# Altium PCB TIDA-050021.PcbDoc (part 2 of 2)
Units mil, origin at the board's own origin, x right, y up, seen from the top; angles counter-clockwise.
Board outline 3800 x 2400 mil, 4 copper layers (Top Layer, Signal Layer 1, Signal Layer 2, Bottom Layer), stack 51.2 mil thick; 78 components, 31 nets, 172 pads, 126 vias.
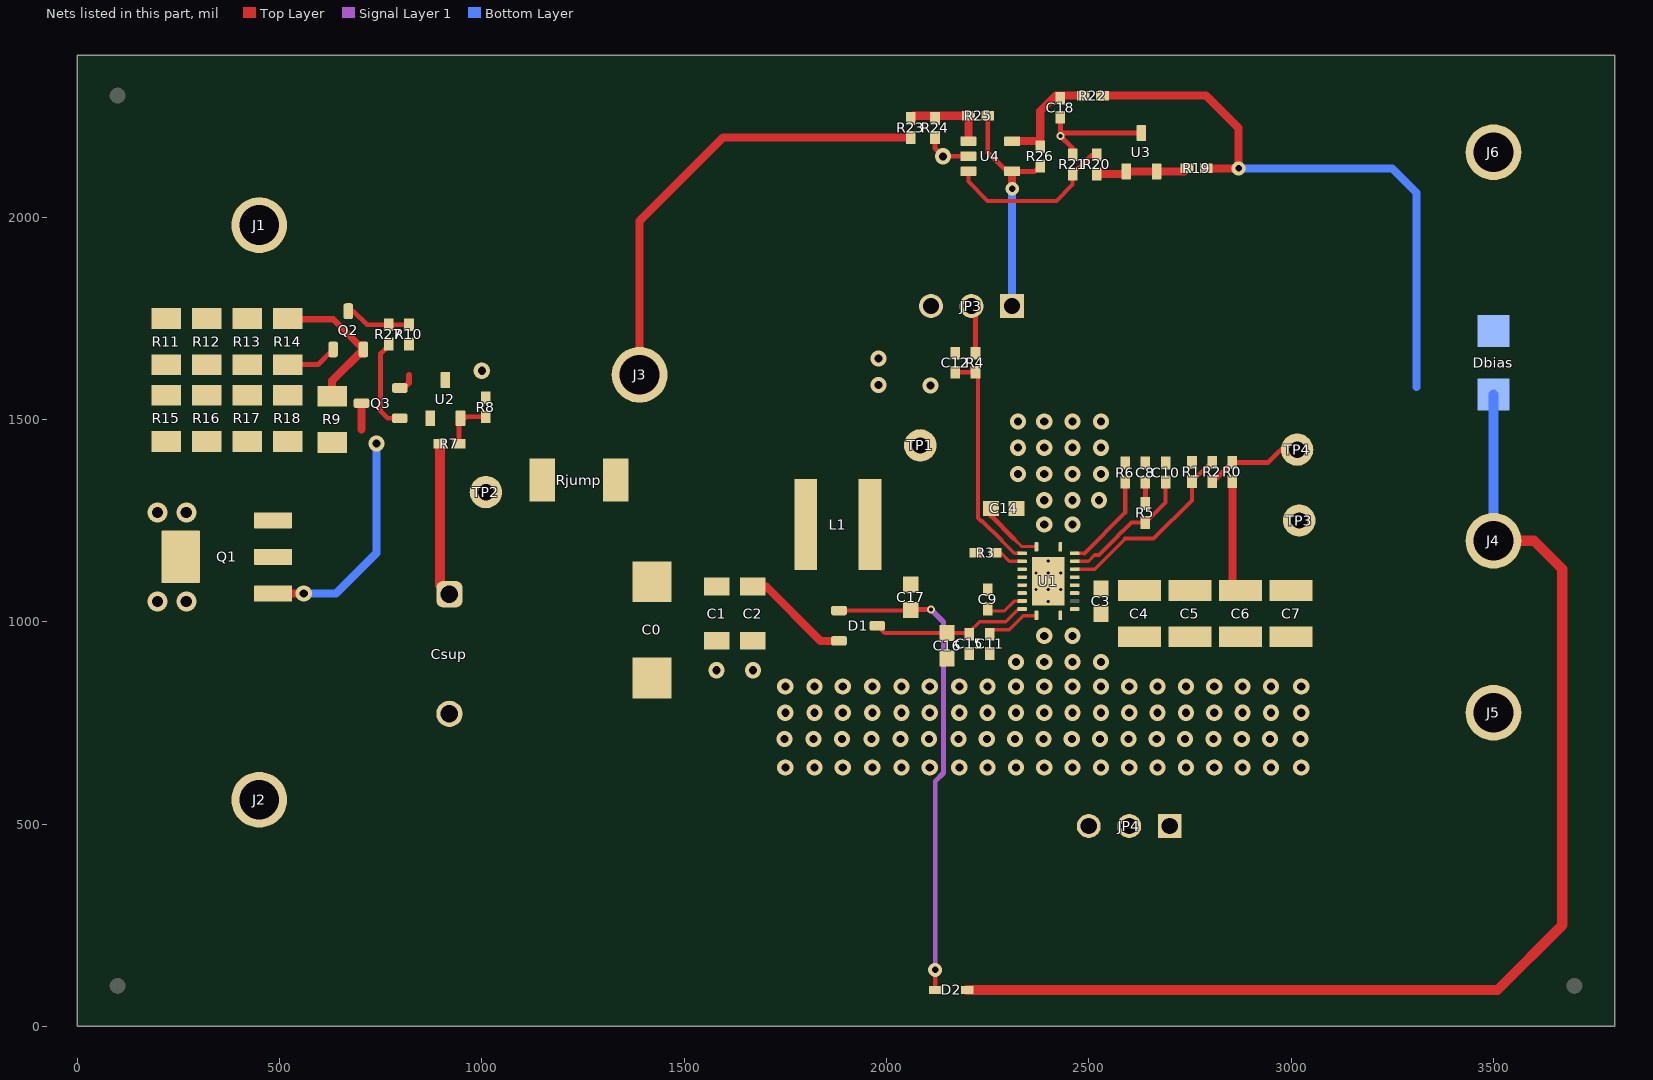
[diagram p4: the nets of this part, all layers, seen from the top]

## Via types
v1: diameter 40, hole 20, Top Layer to Bottom Layer, 108 vias
v2: diameter 19.68, hole 7.87, Top Layer to Bottom Layer, 8 vias
v3: diameter 34, hole 16, Top Layer to Bottom Layer, 4 vias
v4: diameter 50, hole 28, Top Layer to Bottom Layer, 4 vias
v5: diameter 20, hole 10, Top Layer to Bottom Layer, 2 vias

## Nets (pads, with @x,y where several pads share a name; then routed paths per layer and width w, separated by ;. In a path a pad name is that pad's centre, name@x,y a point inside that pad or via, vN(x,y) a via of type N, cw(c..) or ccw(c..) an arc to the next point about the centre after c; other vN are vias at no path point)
2.5V: R7.1 R8.2 U2.2 | length 142.5
  Top Layer w12: U2.2@941.16,1506.38 R8.2@1010,1506.38 ; R7.1@943.62,1440 943.62,1488.98 961.09,1506.45
AGND: C0.2 C1.2 C2.2 C3.2 C4.2 C5.2 C6.2 C7.2 C8.2 C10.2 C11.1 C12.2 C14.1 C15.2 C16.2 C18.2 Csup.2 J2.1 J5.1 JP3.3 JP4.1 JP4.2 JP4.3 Q3.2 R1.1 R6.1 R8.1 R10.1 R21.1 R24.1 U1.11 U1.12 U1.20 U1.21@2400,1100 U2.3 U3.3 U4.2 | length 467.8
  Top Layer w12: Q3.2@797.24,1577.4 Q3.2@807.4,1577.4 ; R24.1@2120,2196.38 2120,2170 2139.8,2150.2 U4.2@2202.43,2150.2 U4.2@2205.85,2153.62 ; C18.2@2430,2246.38 v5(2430,2200) 2460,2170 R21.1@2460,2153.62 ; 2437.24,2207.24 U3.3@2630,2207.24
  Top Layer w15: Q3.2@807.4,1577.4 820,1590 820,1610
  other v1: 1750,640 1822,640 1892,640 1965,640 2037,640 2107,640 2180,640 2250,640 2320,640 2390,640 2460,640 2530,640 2600,640 2670,640 2740,640 2810,640 2880,640 2950,640 3025,640 1748,710 1820,710 1890,710 1963,710 2035,710 2105,710 2178,710 2248,710 2318,710 2388,710 2458,710 2528,710 2598,710 2668,710 2738,710 2808,710 2878,710 2948,710 3023,710 1750,775 1822,775 1892,775 1965,775 2037,775 2107,775 2180,775 2250,775 2320,775 2390,775 2460,775 2530,775 2600,775 2670,775 2740,775 2810,775 2880,775 2950,775 3025,775 1750,840 1822,840 1892,840 1965,840 2037,840 2107,840 2180,840 2250,840 2320,840 2390,840 2460,840 2530,840 2600,840 2670,840 2740,840 2810,840 2880,840 2950,840 3025,840 1580,880 1670,880 2320,900 2390,900 2460,900 2530,900 2390,965 2460,965 2390,1240 2460,1240 2390,1300 2460,1300 2525,1300 2325,1365 2390,1365 2460,1365 2530,1365 2325,1430 2390,1430 2460,1430 2530,1430 2325,1495 2390,1495 2460,1495 2530,1495 2109,1584 1980,1585 1000,1620 1980,1650 2140,2150
  other v2: 2400,1049.8 2369.49,1079.33 2400,1079.33 2430.51,1079.33 2369.49,1120.67 2400,1120.67 2430.51,1120.67 2400,1150.2
BOOT: C9.2 U1.8 | length 90.1
  Top Layer w8: C9.2@2255,1026.38 2291.38,1026.38 2315.78,1050.78 U1.8@2335.04,1050.78
COMP: C10.1 R5.2 U1.18 | length 335.6
  Top Layer w8: U1.18@2464.96,1149.21 2499.21,1149.21 2515,1165
  Top Layer w10: 2515,1165 2525,1165 2572.13,1212.13 2572.13,1212.4 2582.6,1222.87 2582.87,1222.87 2605,1245 R5.2@2640,1245 2690,1295 C10.1@2690,1345
EN: C12.1 R4.2 U1.2 | length 539.6
  Top Layer w8: 2285,1200 2316.11,1168.89 U1.2@2335.04,1168.89
  Top Layer w10: C12.1@2170,1616.38 R4.2@2220,1616.38 ; 2225.94,1600.43 2225.94,1255.97 2233.49,1248.43 2236.57,1248.43 2285,1200
EN1: JP3.1 R25.2 R26.1 U4.4 | length 578.4
  Top Layer w12: R25.2@2250.18,2250.2 2250.18,2159.82 2297.21,2112.79 U4.4@2310.69,2112.79 2366.42,2112.79 R26.1@2380,2126.38
  Top Layer w20: v3(2310.69,2070) U4.4@2310.69,2112.79
  Bottom Layer w20: JP3.1@2310,1780 2310,2069.31 v3(2310.69,2070)
FB: R1.2 R2.1 U1.17 | length 476.6
  Top Layer w8: U1.17@2464.96,1129.52 2514.52,1129.52 2590,1205
  Top Layer w10: 2590,1205 2660,1205 2755,1300 R1.2@2755,1346.38 2802.24,1393.62 R2.1@2805,1393.62
FSW: R3.1 U1.3 | length 75
  Top Layer w8: R3.1@2268.62,1170 2283,1170 2303.79,1149.21 U1.3@2335.04,1149.21
ILIM: R6.2 U1.19 | length 241.9
  Top Layer w8: U1.19@2464.96,1168.89 2488.89,1168.89
  Top Layer w10: 2488.89,1168.89 2590,1270
  Top Layer w12: 2590,1270 R6.2@2590,1345
NetC8_1: C8.1 R5.1 | length 52.8
  Top Layer w12: R5.1@2640,1292.24 C8.1@2640,1345
NetC17_2: C17.2 D1.1 D2.1 | length 1190.4
  Top Layer w10: D1.1@1882.76,1027.4 2058.9,1027.4 C17.2@2060,1028.5
  Top Layer w12: C17.2@2060,1028.5 2061.5,1030 v5(2110,1030) ; D2.1@2120.63,90 v3(2120.63,139.37)
  Signal Layer 1 w12: v5(2110,1030) 2140.87,999.13 2140.87,625.97 2120.63,605.72 v3(2120.63,139.37) v3(2120,140)
NetJP3_2: JP3.2 R4.1 | length 116.4
  Top Layer w12: R4.1@2220,1663.62 JP3.2@2220,1780
NetQ1_1: Q1.1 Q3.3 R9.2 U2.1 | length 652.7
  Top Layer w12: v1@559.45,1069.45 v1(560,1070) ; R9.2@630,1462.91 R9.2@642.91,1450 ; v1@737.87,1440 v1(740,1440)
  Top Layer w20: Q1.1@484.17,1069.45 v1@559.45,1069.45 ; 702.76,1475.12 Q3.3@702.76,1540
  Bottom Layer w20: v1(560,1070) 640,1070 740,1170 v1(740,1440)
NetQ1_2: Q1.2 Q1.4 R15.2 R16.2 R17.2 R18.2 | length 23.4
  Top Layer w20: Q1.4@272.36,1176.54 Q1.4@288.9,1160
  other v4: 198.74,1050 270,1050 198.74,1270 270,1270
NetQ2_1: Q2.1 R11.2 R12.2 R13.2 R14.2 R15.1 R16.1 R17.1 R18.1 | length 142.3
  Top Layer w12: R14.2@520,1635.28 595.12,1635.28 Q2.1@632.6,1672.76
  Top Layer w20: R11.2@210,1630 R11.2@220,1620
NetQ2_3: Q2.3 R10.2 R27.1 | length 163.9
  Top Layer w12: Q2.3@670,1767.24 682.76,1767.24 716.38,1733.62 R27.1@770,1733.62 R10.2@820,1733.62
NetQ3_1: Q3.1 R27.2 | length 229.1
  Top Layer w12: R27.2@770,1686.38 770,1682.44 750,1662.44 750,1520 767.4,1502.6 Q3.1@797.24,1502.6
NetR0_1: R0.1 R2.2 TP4.1 | length 237.9
  Top Layer w12: R2.2@2805,1346.38 2807.76,1346.38 R0.1@2855,1393.62 2943.62,1393.62 TP4.1@3000,1450
NetR19_2: R19.2 R20.1 U3.1 U3.2 | length 228.7
  Top Layer w20: R20.1@2520,2106.38 2586.22,2106.38 U3.1@2592.6,2112.76 U3.2@2667.4,2112.76 2735.5,2112.76 R19.2@2742.94,2120.2
NetR23_1: R23.1 R24.2 R25.1 U4.1 | length 208.5
  Top Layer w20: R23.1@2060,2243.62 2066.57,2250.2 R25.1@2202.94,2250.2 2202.94,2188.11 U4.1@2202.43,2187.6
SS: C11.2 U1.10 | length 134.8
  Top Layer w8: C11.2@2255,968.62 2266.38,980 2303.32,980 2337.82,1014.5 2369.62,1014.5 U1.10@2370.48,1015.35
SVin: C15.1 C16.1 D1.3 U1.9 | length 396.3
  Top Layer w8: C15.1@2205,968.62 2205,975 2230,1000 2295,1000 2326.1,1031.1 U1.9@2335.04,1031.1
  Top Layer w10: D1.3@1977.24,990 1995.75,971.5 C16.1@2150,971.5 2202.13,971.5 C15.1@2205,968.62
SW: C9.1 C17.1 L1.2 R3.2 TP1.1 U1.4 U1.5 U1.6 U1.7
V+: C18.1 R22.1 R26.2 U4.5 | length 269.2
  Top Layer w20: U4.5@2310.69,2187.6 2380,2187.6 R26.2@2380,2173.62 ; 2380,2198 2380,2261.65 2418.35,2300 R22.1@2486.38,2300
Vbias: Dbias.2 J6.1
Vcc: C14.2 U1.1 | length 175
  Top Layer w8: 2315,1205 2334.19,1185.81 2334.19,1185.49 2370.48,1185.49 U1.1@2370.48,1184.65
  Top Layer w12: C14.2@2258.5,1280 2258.5,1261.5 2315,1205
  Top Layer w15: C14.2@2260,1288.5 C14.2@2268.5,1280
Vin: J1.1 Q2.2 R9.1 R11.1 R12.1 R13.1 R14.1 | length 352.5
  Top Layer w12: R14.1@520,1749.45 R14.1@521.89,1747.56
  Top Layer w16: R14.1@521.89,1747.56 632.6,1747.56 Q2.2@707.4,1672.76
  Top Layer w20: R9.1@630,1571.5 630,1595.35 Q2.2@707.4,1672.76
Vout: C3.1 C4.1 C5.1 C6.1 C7.1 D2.2 Dbias.1 J4.1 R0.2 R19.1 R22.2 TP3.1 U1.14 U1.15 U1.16 | length 4742.6
  Top Layer w20: R22.2@2540,2300 2790,2300 2870,2220 v3(2870,2120) 2790.38,2120 R19.1@2790.18,2120.2 ; R0.2@2855,1346.38 2855,1097.09 C6.1@2875,1077.09
  Top Layer w25: D2.2@2199.37,90 3510,90 3670,250 3670,1130 3600,1200 J4.1@3500,1200
  Bottom Layer w20: v3(2870,2120) 3250,2120 3310,2060 3310,1580
  Bottom Layer w25: J4.1@3500,1200 Dbias.1@3500,1561.26
Vref: R20.2 R21.2 U4.3 | length 425
  Top Layer w10: U4.3@2202.43,2112.79 2202.43,2087.57 2250,2040 2420,2040 2460,2080 R21.2@2460,2106.38 2507.24,2153.62 R20.2@2520,2153.62
VSUP: Csup.1 Q1.3 R7.2 Rjump.2 TP2.1 | length 382.1
  Top Layer w25: R7.2@896.38,1440 896.38,1091.26 Csup.1@920,1067.64
VSUP1: C0.1 C1.1 C2.1 D1.2 J3.1 L1.1 R23.2 Rjump.1 | length 1413.9
  Top Layer w20: J3.1@1390,1600 1390,1990 1596.38,2196.38 R23.2@2060,2196.38 ; C2.1@1670,1086.93 1703.07,1086.93 1837.4,952.6 D1.2@1882.76,952.6
pads on no net: FID1.1 FID2.1 FID3.1 U1.13 U1.21@2377.95,1058.66 U1.21@2377.95,1100 U1.21@2377.95,1141.34 U1.21@2422.05,1058.66 U1.21@2422.05,1100 U1.21@2422.05,1141.34

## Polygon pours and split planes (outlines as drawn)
AGND on Top Layer "TOP_LAYER_AGND_P008" (solid, remove dead copper, pour order 8): 1900,1560 1900,2000 3500,2000 3600,1900 3600,1380 2770,1380 2580,1380 2560,1360 2560,1270 2430.51,1140.51 2430.51,1120.67 2369.49,1120.67 2370,1121.18 2370,1181.18 2301.18,1250 2280,1250 2280,1560
AGND on Top Layer "TOP_LAYER_AGND_P006" (solid, remove dead copper, pour order 6): 400,980 1700,980 1750,930 2270,930 2370,1030 2370,1050 2440,1050 2452,1038 2554,1038 2592,1000 3600,1000 3600,300 3500,200 500,200 400,300
SW on Top Layer "TOP_LAYER_SW_P004" (solid, remove dead copper, pour order 4): 1900,1465 1965,1465 2105,1465 2200,1370 2200,1240 2231.24,1208.76 2231.24,1158.17 2249.41,1140 2300,1140 2306,1134 2345,1134 2345,1060 2235,1060 1900,1060
VSUP1 on Top Layer "TOP_LAYER_VSUP1_P002" (solid, remove dead copper, pour order 2): 1240,1940 1300,2000 1840,2000 1840,1040 1240,1040
Vout on Top Layer "TOP_LAYER_VOUT_P000" (solid, remove dead copper, pour order 0): 2485,1115 2525.09,1115.09 2590,1180 2670,1180 2790,1300 3600,1300 3600,1030 2600,1030 2568,1062 2485,1062 2482,1065 2454,1065 2454,1115
Vin on Top Layer "TOP_LAYER_VIN_P012" (solid, remove dead copper, pour order 12): 200,1900 300,2000 570,2000 570,1720 200,1720
NetQ2_1 on Top Layer "TOP_LAYER_NETQ2_1_P014" (solid, remove dead copper, pour order 14): 200,1660 566.26,1660 566.26,1530 200,1530
NetQ1_2 on Top Layer "TOP_LAYER_NETQ1_2_P016" (solid, remove dead copper, pour order 16): 180,1480 566.26,1480 566.26,1366.26 530,1330 400,1330 400,1210 425.12,1184.88 425.12,1180 530,1180 530,1140 425.12,1140 400,1114.88 400,990 180,990
AGND on Top Layer "TOP_LAYER_AGND_P026" (solid, remove dead copper, pour order 26): 810,1700 1000,1700 1020,1680 1020,1540 1000,1540 940,1600 810,1600
VSUP on Top Layer "TOP_LAYER_VSUP_P042" (solid, remove dead copper, pour order 42): 440,1310 910,1310 1050,1450 1050,1560 1070,1580 1190,1580 1190,1040 600,1040 600,1180 570,1210 440,1210
NetQ1_1 on Top Layer "TOP_LAYER_NETQ1_1_P044" (solid, remove dead copper, pour order 44): 640,1460 640,1475 645,1480 826.1,1480 841.1,1495 841.1,1520 879.69,1520 885,1514.69 885,1485 800,1400 595,1400 595,1455 637.91,1455
Vout on Bottom Layer "BOTTOM_LAYER_VOUT_P038" (solid, remove dead copper, pour order 38): 3300,1600 3700,1600 3700,1130 3670,1100 3322.5,1100 3300,1130 3300,1150
NetQ1_2 on Bottom Layer "BOTTOM_LAYER_NETQ1_2_P022" (solid, remove dead copper, pour order 22): 180,1420 520,1420 520,990 180,990
AGND on Bottom Layer "BOTTOM_LAYER_AGND_P034" (solid, remove dead copper, pour order 34): 1064.71,1900 3100,1900 3250,1750 3250,360 3090,200 500,200 400,300 400,830 550,980 930,980 980,1030 980,1815.29
Vbias on Bottom Layer "BOTTOM_LAYER_VBIAS_P040" (solid, remove dead copper, pour order 40): 3340,2300 3700,2300 3700,1690 3340,1690
NetQ1_2 on Signal Layer 1 "SIGNAL_LAYER_1_NETQ1_2_P018" (solid, remove dead copper, pour order 18): 510,1400 510,990 160,990 160,1400
AGND on Signal Layer 1 "SIGNAL_LAYER_1_AGND_P030" (solid, remove dead copper, pour order 30): 1100,2000 3500,2000 3600,1900 3600,300 3500,200 500,200 400,300 400,830 550,980 930,980 980,1030 980,1880
NetQ1_2 on Signal Layer 2 "SIGNAL_LAYER_2_NETQ1_2_P020" (solid, remove dead copper, pour order 20): 160,1400 510,1400 510,990 160,990
AGND on Signal Layer 2 "SIGNAL_LAYER_2_AGND_P032" (solid, remove dead copper, pour order 32): 980,1900 1290,2210 3290,2210 3600,1900 3600,300 3500,200 500,200 400,300 400,830 550,980 930,980 980,1030

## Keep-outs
Keep-Out Layer:
  text ".Layer_Name" at 577,-858.49 h30

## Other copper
Top Layer:
  pour cut-out: 400,979.8 549.97,979.97 400.98,830.98 400.98,980
  text ".Layer_Name" at 577,-858.49 h30
Bottom Layer:
  text ".Layer_Name" at 577,-858.49 h30

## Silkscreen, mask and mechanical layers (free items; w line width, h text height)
Top Overlay:
  text "Vbias" at 3410,2280 h30
  text "VIN" at 400,2100 h50
  text "OFF" at 2060,1860 h30
  text "EN" at 2180,1860 h30
  text "ON" at 2280,1860 h30
  text "Vsup" at 1500,1520 h50
  text "VO" at 3650,1160 h50
  text "GND" at 3635,730 h50
  text "GND" at 380,380 h50
  text "GND" at 2500,360 h50
  text "TIDA-050021" at 1000,235 h60
  text ".Layer_Name" at 577,-858.49 h30
Bottom Overlay:
  text ".Layer_Name" at 577,-858.49 h30
Top Paste:
  text ".Layer_Name" at 577,-858.49 h30
Bottom Paste:
  text ".Layer_Name" at 577,-858.49 h30
Top Solder:
  text ".Layer_Name" at 577,-858.49 h30
  text ".Layer_Name" at 577,-858.49 h30
Bottom Solder:
  text ".Layer_Name" at 577,-858.49 h30
Drill Guide:
  text ".Layer_Name" at 577,-858.49 h30
M1 Board Outline:
  lines w10: 0,0 0,2400 ; 0,0 3800,0 ; 0,0 0,2400 ; 0,0 3800,0 ; 0,2400 3800,2400 ; 0,2400 3800,2400 ; 3800,0 3800,2400 ; 3800,0 3800,2400
  text ".Layer_Name" at 577,-858.49 h30
M2 Board Dimensions:
  rectangle: 125,-400 500,-275
  rectangle: 0,-275 125,-150
  lines w7: 0,-275 1000,-275 ; 125,-400 125,-150 ; 250,-400 250,-150 ; 500,-400 500,-150 ; 750,-400 750,-150 ; 0,-400 0,-150 1000,-150 1000,-400 0,-400
  text ".Layer_Name" at 577,-858.49 h30
M3 3D STEP Top:
  text ".Layer_Name" at 577,-858.49 h30
M4 3D STEP Bottom:
  text ".Layer_Name" at 577,-858.49 h30
M5 Assembly Top:
  lines w10: -292,-930.17 6308,-930.17 ; -292,-726.83 6310,-726.83 ; -292,-523.5 -292,-1133.5 3713,-1133.5 6310,-1133.5 6310,-523.5 -291.5,-523.5 -291.5,-1133.5 1284,-1133.5 ; 2173,-1133.5 2173,-523.5 ; 3440,-726.83 3440,-523.5 ; 4280,-726.83 4280,-523.5 ; 4902,-1140 4902,-937.17
  text "COMPONENTS MARKED 'DNP' SHOULD NOT BE POPULATED." at 1153.5,-318.5 h30
  text "ASSEMBLY VARIANT:" at 1153,-434 h30
  text ".VariantName" at 2189,-434 h30
  text "PCB VIEWED FROM TOP SIDE" at -228.5,-655.67 h30
  text "BOARD #:" at 2248,-655.67 h30
  text ".PRJ_Number" at 2793.5,-655.67 h30
  text "REV:" at 3638,-655.67 h30
  text ".PCB_Rev" at 3929.5,-655.67 h30
  text "SVN REV:" at 4476,-655.67 h30
  text ".VersionControl_RevNumber" at 4982,-655.67 h30
  text "TID #:" at 2248,-859 h30
  text ".TID" at 2793.5,-859 h30
  text "PLOT NAME =" at -228.5,-1064.34 h30
  text ".plot_File_Name" at 577,-1064.34 h30
  text "GENERATED    :" at 2250,-1064.34 h30
  text ".Print_Date" at 3119.5,-1064.34 h30
  text ".Print_Time" at 3848.5,-1064.34 h30
  text "TEXAS INSTRUMENTS" at 5113,-1064.34 h30
M6 Assembly Bottom:
  lines w10: -292.5,-727.33 6309.5,-727.33 ; -290.5,-930.67 6309.5,-930.67 ; 1115.5,-1140.5 1115.5,-937.67 ; 1737.5,-727.33 1737.5,-524 ; 2577.5,-727.33 2577.5,-524 ; 3844.5,-1134 3844.5,-524 ; 4733.5,-1134 6309,-1134 6309,-524 -292.5,-524 -292.5,-1134 2304.5,-1134 6309.5,-1134 6309.5,-524
  text "COMPONENTS MARKED 'DNP' SHOULD NOT BE POPULATED." at 6102,-318 h30
  text ".VariantName" at 5058,-434 h30
  text "ASSEMBLY VARIANT:" at 6097,-434 h30
  text ".VersionControl_RevNumber" at 1035.5,-656.17 h30
  text "SVN REV:" at 1541.5,-656.17 h30
  text ".PCB_Rev" at 2088,-656.17 h30
  text "REV:" at 2379.5,-656.17 h30
  text ".PRJ_Number" at 3224,-656.17 h30
  text "BOARD #:" at 3769.5,-656.17 h30
  text "PCB VIEWED FROM BOTTOM SIDE" at 6246,-656.17 h30
  text ".TID" at 3224,-859.5 h30
  text "TID #:" at 3769.5,-859.5 h30
  text "TEXAS INSTRUMENTS" at 904.5,-1064.84 h30
  text ".Print_Time" at 2169,-1064.84 h30
  text ".Print_Date" at 2898,-1064.84 h30
  text "GENERATED    :" at 3767.5,-1064.84 h30
  text ".plot_File_Name" at 5440.5,-1064.84 h30
  text "PLOT NAME =" at 6246,-1064.84 h30
M9 Title Sheet:
  drawing of 57 lines, arcs and shapes, not listed
  text "1" at 739.84,8036.5 h30
  text "2" at 3235.5,8036.5 h30
  text "3" at 5724.84,8036.5 h30
  text "4" at 8231.51,8036.5 h30
  text "5" at 10730.5,8036.5 h30
  text "6" at 13235.5,8036.5 h30
  text "A" at -416.5,6893.5 h30
  text "A" at 14383.5,6893.5 h30
  text "B" at -416.5,4513.5 h30
  text "B" at 14383.5,4513.5 h30
  text "C" at -416.5,2138.5 h30
  text "C" at 14383.5,2138.5 h30
  text "PROJECT TITLE:" at 11343.5,277.5 h30
  text ".PRJ_Title" at 11393.5,144.17 h30
  text "DESIGNED FOR:" at 11343.5,-23.5 h30
  text ".PRJ_Customer" at 11393.5,-163.5 h30
  text "D" at -416.5,-231.5 h30
  text "D" at 14383.5,-231.5 h30
  text "FILE NAME:" at 11343.5,-323.5 h30
  text ".PCB_File_Name_No_Path" at 11393.5,-443.5 h30
  text "Texas Instruments (TI) and/or its licensors do not warrant the accuracy or completeness of this specification" at 6374,-605.34 h30
  text "ENGINEER:" at 11343.5,-613.5 h30
  text "LAYOUT BY:" at 12848.5,-613.5 h30
  text "or any information contained therein. TI and/or its licensors do not warrant that this design will meet" at 6329.01,-718 h30
  text ".PRJ_Engineer" at 11393.5,-768.49 h30
  text ".PCB_Layout" at 12899,-768.49 h30
  text "the specifications, will be suitable for your application or fit for any particular purpose, or will operate in" at 6329.01,-830.67 h30
  text ".Layer_Name" at 577,-858.49 h30
  text "ALTIUM DESIGNER VERSION:" at 12848.5,-923.5 h30
  text "an implementation. TI and/or its licensors do not warrant that the design is production worthy. You should" at 6329.01,-943.33 h30
  text "completely validate and test your design implementation to confirm the system functionality for your application." at 6374,-1056 h30
  text ".print_Scale" at 11393.5,-1056.83 h30
  text ".Application_BuildNumber" at 12899,-1056.83 h30
  text "1" at 739.84,-1263.5 h30
  text "2" at 3235.5,-1263.5 h30
  text "3" at 5724.84,-1263.5 h30
  text "4" at 8231.51,-1263.5 h30
  text "5" at 10730.5,-1263.5 h30
  text "6" at 13235.5,-1263.5 h30
M10 Fab Notes:
  drawing of 189 lines, arcs and shapes, not listed
  text "DESIGN INFORMATION" at 12382.02,6356.17 h30
  text "MIN. TRACK WIDTH:" at 11737.46,6224.05 h30
  text "8" at 12833.7,6224.05 h30
  text "MIL" at 12988.46,6224.05 h30
  text "MIN. CLEARANCE:" at 11737.46,6099.92 h30
  text "0.1" at 12773.7,6099.93 h30
  text "mm" at 12988.46,6099.92 h30
  text "MIN. VIA PAD SIZE:" at 11737.46,5975.8 h30
  text "18" at 12803.71,5975.8 h30
  text "MIL" at 12988.46,5975.8 h30
  text "0.05mm (2MIL)" at 12432.46,5845.9 h30
  text "MINIMUM ANNULAR RING" at 11408.23,5837.67 h30
  text "EXTERNAL" at 13140.46,5837.67 h30
  text "PER" at 11608.23,5727.55 h30
  text "IPC-D-275 CLASS 2 LEVEL C" at 11828.23,5727.54 h30
  text "MIL, HOLES" at 13316.46,5627.07 h30
  text "+/-" at 12924,5618.48 h30
  text "+/-" at 13778,5618.48 h30
  text "REGISTRATION TOLERANCES:" at 11408.23,5617.42 h30
  text "METAL" at 12608,5617.42 h30
  text "5" at 13184.2,5617.42 h30
  text "3" at 14017.2,5617.42 h30
  text "MIL" at 14133.46,5617.42 h30
  text "HOLE SIZE TOLERANCE (UNLESS OTHERWISE SPECIFIED):" at 11408.23,5519.1 h30
  text "+/-" at 13778,5516.23 h30
  text "3" at 14017.2,5515.17 h30
  text "MIL" at 14133.46,5515.17 h30
  text "MATERIAL:" at 11333.46,5377.52 h30
  text "FR-4 High Tg" at 12319.9,5249 h30
  text "X" at 12175.46,5241.01 h30
  text "FR-408" at 11754.46,5236.49 h30
  text "OTHER" at 13242.46,5236.49 h30
  text "X" at 13250.46,5101.01 h30
  text "62 MIL (1.6mm) +/-10%" at 12074.56,5093.46 h30
  text "47mil(1.2mm)" at 13655,5089 h30
  text "THICKNESS:" at 11408.23,5085.24 h30
  text "OTHER" at 13359.46,5085.24 h30
  text "TOLERANCE:" at 11408.23,4946.92 h30
  text "X" at 12256.46,4946.92 h30
  text "ANSI IPC-6012 TYPE 3 CLASS 2" at 12434.48,4946.92 h30
  text "OTHER +/-" at 12434.46,4802.73 h30
  text "BOW & TWIST:" at 11408.23,4657.54 h30
  text "X" at 12256.46,4657.54 h30
  text "ANSI IPC-6012 TYPE 3 CLASS 2" at 12434.48,4657.54 h30
  text "OTHER +/-" at 12434.46,4510.85 h30
  text "DRILLING:" at 11333.46,4380.23 h30
  text "NC_DRILL FILES" at 13094.46,4275.04 h30
  text "REFERENCE:" at 11408.23,4271.1 h30
  text "X" at 12065.46,4271.01 h30
  text "AS SHOWN" at 12243.46,4271.1 h30
  text "X" at 12966.46,4271.1 h30
  text "OTHER" at 13392.46,4128.85 h30
  text "PTH COPPER THICKNESS:" at 11407.91,4125.32 h30
  text "X" at 12547.14,4125.32 h30
  text "20-30 um" at 12675.14,4125.32 h30
  text "BOARD FINISH:" at 11333.46,3977.73 h30
  text "SILKSCREEN:" at 11488.68,3867.6 h30
  text "X" at 12446.46,3867.6 h30
  text "TOP" at 12563.46,3867.6 h30
  text "X" at 12956.46,3867.6 h30
  text "BOTTOM" at 13074.46,3867.6 h30
  text "SILKSCREEN COLOR:" at 11488.68,3712.41 h30
  text "X" at 12445.46,3712.41 h30
  text "WHITE" at 12563.46,3712.41 h30
  text "OTHER" at 13074.46,3712.41 h30
  text "X" at 12576.46,3568.96 h30
  text "GREEN" at 12694.46,3568.96 h30
  text "OTHER" at 13312.46,3568.96 h30
  text "SOLDER RESIST COLOR:" at 11488.68,3562.1 h30
  text "X" at 12576.46,3414.71 h30
  text "MATTE" at 12694.46,3414.71 h30
  text "SEMI-GLOSS" at 13312,3414.07 h30
  text "IMMERSION GOLD (ENIG)" at 12394.46,3241.94 h30
  text "ENEPIG" at 13732,3234.72 h30
  text "SURFACE FINISH:" at 11333.46,3233.72 h30
  text "X" at 12216.46,3233.72 h30
  text "IMM. TIN/SILVER OR EQUIV" at 11663,3096.4 h30
  text "OTHER" at 13094.46,3092.47 h30
  text "ARRAY/PANEL:" at 11333.46,2937.09 h30
  text "CUT AND TRIM PER M1 BOARD OUTLINE" at 12394.46,2928.87 h30
  text "N.C. ROUTE" at 12394.46,2792.9 h30
  text "X" at 13082.46,2792.9 h30
  text "V. SCORE" at 13260.46,2792.9 h30
  text "CERTIFICATION:" at 11333.46,2663.77 h30
  text "MATERIALS AND WORKMANSHIP FOR ALL PCBS" at 12058.46,2663.77 h30
  text "TO MEET OR EXCEED THE REQUIREMENTS OF:" at 12058.46,2569.71 h30
  text "X" at 11695.97,2441.08 h30
  text "ANSI IPC-A-600F CLASS ->" at 11823.96,2441.08 h30
  text "X" at 13471.97,2441.08 h30
  text "2" at 13581.96,2441.08 h30
  text "1" at 13266.96,2439.58 h30
  text "3" at 13935.96,2439.58 h30
  text "X" at 12507.97,2293.39 h30
  text "RoHS" at 12635.96,2293.39 h30
  text "OTHER" at 13280.36,2293.39 h30
  text "PER ORDER" at 13677.42,2293.39 h30
  text "ALL BOARDS MUST MEET OR EXCEED UL94-V0 REQUIREMENTS." at 11361,2139.57 h30
  text "PCB MUST BEAR THE UL94V-0 UL REGISTERED MATERIAL ID NUMBER" at 11361,2023.5 h30
  text "ADDITIONAL REQUIREMENTS:" at 11333.46,1854.08 h30
  text "MICROSECTION:" at 11408.23,1746.95 h30
  text "YES" at 12313.96,1746.95 h30
  text "REQUIRED" at 13175.46,1602.62 h30
  text "BARE BOARD ELEC. TEST:" at 11408.23,1599.76 h30
  text "NONE" at 12713.96,1599.76 h30
  text "X" at 13057.46,1599.76 h30
  text "PER ORDER" at 13767.46,1599.76 h30
  text "XX MIL VIAS REQUIRE NON-CONDUCTIVE FILL AND PLANARIZE" at 11576.38,1394.82 h30
  text "XX MIL VIAS REQUIRE CONDUCTIVE FILL AND PLANARIZE" at 11584.38,1290.84 h30
  text "OUTER XX MIL TRACES REQUIRE 50 OHM SINGLE-ENDED IMPEDANCE" at 11583.39,1127.46 h30
  text "LAYER 2 & 3 (INNER LAYERS) XX MIL WIDE, XX MIL SPACE / TRACES REQUIRE 100 OHM DIFFERENTIAL IMPEDANCE" at 11575.39,891.74 h30
  text ".Layer_Name" at 577,-858.49 h30
M11 Gerber Information:
  lines w10: -292,-930.17 6308,-930.17 ; -292,-726.83 6310,-726.83 ; -292,-523.5 -292,-1133.5 3713,-1133.5 6310,-1133.5 6310,-523.5 -291.5,-523.5 -291.5,-1133.5 1284,-1133.5 ; 2173,-1133.5 2173,-523.5 ; 3440,-726.83 3440,-523.5 ; 4280,-726.83 4280,-523.5 ; 4902,-1140 4902,-937.17
  text "ALL ARTWORK VIEWED FROM TOP SIDE" at -228.5,-655.67 h30
  text "BOARD #:" at 2248,-655.67 h30
  text ".PRJ_Number" at 2793.5,-655.67 h30
  text "REV:" at 3638,-655.67 h30
  text ".PCB_Rev" at 3929.5,-655.67 h30
  text "SVN REV:" at 4476,-655.67 h30
  text ".VersionControl_RevNumber" at 4982,-655.67 h30
  text "LAYER NAME =" at -228.5,-858.49 h30
  text "TID #:" at 2248,-859 h30
  text ".TID" at 2793.5,-859 h30
  text "PLOT NAME =" at -228.5,-1064.34 h30
  text ".plot_File_Name" at 577,-1064.34 h30
  text "GENERATED    :" at 2250,-1064.34 h30
  text ".Print_Date" at 3119.5,-1064.34 h30
  text ".Print_Time" at 3848.5,-1064.34 h30
  text "TEXAS INSTRUMENTS" at 5113,-1064.34 h30
M12 Stackup:
  drawing of 269 lines, arcs and shapes, not listed
  text "Layer" at 4590,5520 h60
  text "Name" at 4993.91,5520 h60
  text "Material" at 5927.65,5520 h60
  text "Thickness" at 6781.42,5520 h60
  text "Constant" at 7425.26,5520 h60
  text "Board Layer Stack" at 7989.12,5520 h60
  text "1" at 4590,5400 h60
  text "Top Overlay" at 4993.91,5400 h60
  text "2" at 4590,5280 h60
  text "Top Solder" at 4993.91,5280 h60
  text "Solder Resist" at 5927.65,5280 h60
  text "0.40mil" at 6781.42,5280 h60
  text "3.5" at 7425.26,5280 h60
  text "3" at 4590,5160 h60
  text "Top Layer" at 4993.91,5160 h60
  text "Copper" at 5927.65,5160 h60
  text "2.80mil" at 6781.42,5160 h60
  text "4" at 4590,5040 h60
  text "Dielectric1" at 4993.91,5040 h60
  text "FR-4" at 5927.65,5040 h60
  text "10.00mil" at 6781.42,5040 h60
  text "4.8" at 7425.26,5040 h60
  text "5" at 4590,4920 h60
  text "Signal Layer 1" at 4993.91,4920 h60
  text "Copper" at 5927.65,4920 h60
  text "2.80mil" at 6781.42,4920 h60
  text "6" at 4590,4800 h60
  text "Dielectric 3" at 4993.91,4800 h60
  text "20.00mil" at 6781.42,4800 h60
  text "4.2" at 7425.26,4800 h60
  text "7" at 4590,4680 h60
  text "Signal Layer 2" at 4993.91,4680 h60
  text "Copper" at 5927.65,4680 h60
  text "2.80mil" at 6781.42,4680 h60
  text "8" at 4590,4560 h60
  text "Dielectric 2" at 4993.91,4560 h60
  text "10.00mil" at 6781.42,4560 h60
  text "4.8" at 7425.26,4560 h60
  text "9" at 4590,4440 h60
  text "Bottom Layer" at 4993.91,4440 h60
  text "Copper" at 5927.65,4440 h60
  text "2.80mil" at 6781.42,4440 h60
  text "10" at 4590,4320 h60
  text "Bottom Solder" at 4993.91,4320 h60
  text "Solder Resist" at 5927.65,4320 h60
  text "0.40mil" at 6781.42,4320 h60
  text "3.5" at 7425.26,4320 h60
  text ".Layer_Name" at 577,-858.49 h30
M13 Component Bodies Top:
  text ".Layer_Name" at 577,-858.49 h30
M14 Component Bodies Bottom:
  text ".Layer_Name" at 577,-858.49 h30
M15 Courtyards Top:
  text ".Layer_Name" at 577,-858.49 h30
M16 Courtyards Bottom:
  text ".Layer_Name" at 577,-858.49 h30
Drill Drawing:
  circle w7: c5325.42,3172.16 r13.79
  lines w7: 5311.63,2937.76 5339.2,2937.76 5325.42,2910.18 5311.63,2937.76 ; 5311.63,2972.23 5325.42,2979.12 5339.2,2972.23 5332.31,2986.02 5339.2,2999.81 5325.42,2992.91 5311.63,2999.81 5318.52,2986.02 5311.63,2972.23 ; 5311.63,3034.28 5339.2,3034.28 5339.2,3061.86 5311.63,3061.86 5311.63,3034.28 ; 5311.63,3110.11 5325.42,3096.33 5339.2,3110.11 5325.42,3123.9 5311.63,3110.11 ; 5311.63,3220.42 5311.63,3227.32 5318.52,3234.21 5311.63,3241.11 5311.63,3248 5318.52,3248 5325.42,3241.11 5332.31,3248 5339.2,3248 5339.2,3241.11 5332.31,3234.21 5339.2,3227.32 5339.2,3220.42 5332.31,3220.42 5325.42,3227.32 5318.52,3220.42 5311.63,3220.42 ; 5311.63,3289.36 5318.52,3289.36 5318.52,3282.47 5332.31,3282.47 5332.31,3289.36 5339.2,3289.36 5339.2,3303.15 5332.31,3303.15 5332.31,3310.05 5318.52,3310.05 5318.52,3303.15 5311.63,3303.15 5311.63,3289.36 ; 5311.63,3351.41 5318.52,3351.41 5325.42,3344.52 5332.31,3351.41 5339.2,3351.41 5332.31,3358.31 5339.2,3365.2 5332.31,3365.2 5325.42,3372.1 5318.52,3365.2 5311.63,3365.2 5318.52,3358.31 5311.63,3351.41
  lines w12: 5286,2891.57 6900.62,2891.57 ; 5286,3387.95 6900.62,3387.95 ; 5454.83,2829.52 5454.83,3450 ; 5620.76,2829.52 5620.76,3450 ; 5938.98,2829.52 5938.98,3450 ; 6068.48,2829.52 6068.48,3450 ; 6255.99,2829.52 6255.99,3450 ; 6617.51,2829.52 6617.51,3450 ; 5286,2829.52 6900.62,2829.52 6900.62,3450 5286,3450 5286,2829.52
  text "Symbol" at 5323.23,3406.57 h36
  text "Quantity" at 5473.44,3406.57 h36
  text "Finished Hole Size" at 5639.38,3406.57 h36
  text "Plated" at 5957.59,3406.57 h36
  text "Hole Type" at 6087.1,3406.57 h36
  text "Drill Layer Pair" at 6274.61,3406.57 h36
  text "Hole Tolerance" at 6636.12,3406.57 h36
  text "8" at 5473.44,3344.52 h30
  text "7.87mil (0.200mm)" at 5639.38,3344.52 h30
  text "PTH" at 5957.59,3344.52 h30
  text "Round" at 6087.1,3344.52 h30
  text "Top Layer - Bottom Layer" at 6274.61,3344.52 h30
  text "2" at 5473.44,3282.47 h30
  text "10.00mil (0.254mm)" at 5639.38,3282.47 h30
  text "PTH" at 5957.59,3282.47 h30
  text "Round" at 6087.1,3282.47 h30
  text "Top Layer - Bottom Layer" at 6274.61,3282.47 h30
  text "4" at 5473.44,3220.42 h30
  text "16.00mil (0.406mm)" at 5639.38,3220.42 h30
  text "PTH" at 5957.59,3220.42 h30
  text "Round" at 6087.1,3220.42 h30
  text "Top Layer - Bottom Layer" at 6274.61,3220.42 h30
  text "108" at 5473.44,3158.37 h30
  text "20.00mil (0.508mm)" at 5639.38,3158.37 h30
  text "PTH" at 5957.59,3158.37 h30
  text "Round" at 6087.1,3158.37 h30
  text "Top Layer - Bottom Layer" at 6274.61,3158.37 h30
  text "4" at 5473.44,3096.33 h30
  text "28.00mil (0.711mm)" at 5639.38,3096.33 h30
  text "PTH" at 5957.59,3096.33 h30
  text "Round" at 6087.1,3096.33 h30
  text "Top Layer - Bottom Layer" at 6274.61,3096.33 h30
  text "10" at 5473.44,3034.28 h30
  text "40.00mil (1.016mm)" at 5639.38,3034.28 h30
  text "PTH" at 5957.59,3034.28 h30
  text "Round" at 6087.1,3034.28 h30
  text "Top Layer - Bottom Layer" at 6274.61,3034.28 h30
  text "2" at 5473.44,2972.23 h30
  text "43.31mil (1.100mm)" at 5639.38,2972.23 h30
  text "PTH" at 5957.59,2972.23 h30
  text "Round" at 6087.1,2972.23 h30
  text "Top Layer - Bottom Layer" at 6274.61,2972.23 h30
  text "6" at 5473.44,2910.18 h30
  text "98.43mil (2.500mm)" at 5639.38,2910.18 h30
  text "PTH" at 5957.59,2910.18 h30
  text "Round" at 6087.1,2910.18 h30
  text "Top Layer - Bottom Layer" at 6274.61,2910.18 h30
  text "144 Total" at 5473.44,2848.13 h30
  text ".Layer_Name" at 577,-858.49 h30
M17 Embedded Cavity:
  text ".Layer_Name" at 577,-858.49 h30
M18 Embedded Assembly:
  text ".Layer_Name" at 577,-858.49 h30
M19 Embedded Keepout:
  text ".Layer_Name" at 577,-858.49 h30

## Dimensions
0,0 to 3800,0 on M2 Board Dimensions
0,0 to 0,2400 on M2 Board Dimensions
0,-400 to 1000,-400 on M2 Board Dimensions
